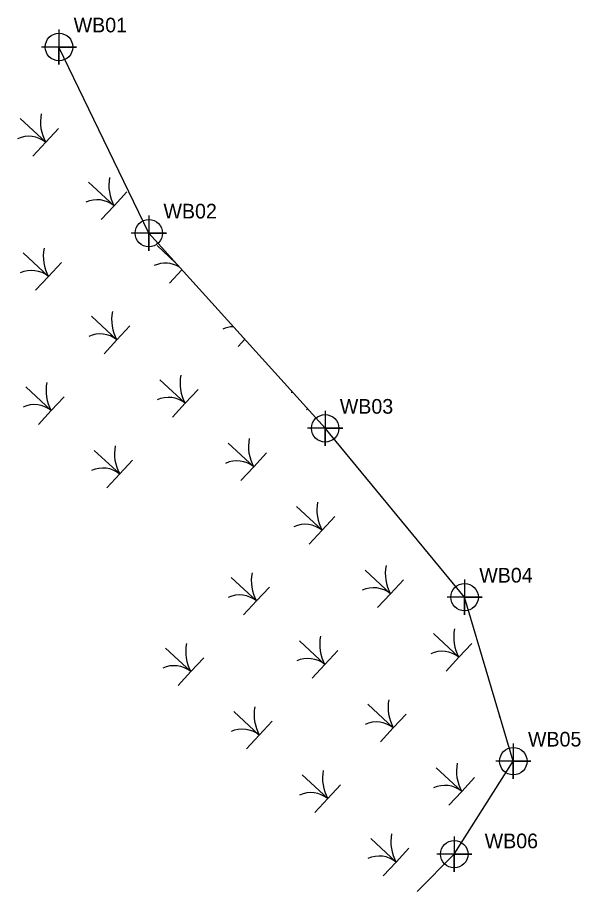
# Model space of a CAD drawing. Extents: x 2130226 to 2130625, y 149525 to 150037.
# Drawn here: x 2130401.6 to 2130497.6, y 149887.6 to 150036.7 of the extents above; entities that cross this region are included whole.
import ezdxf

# ---------------------------------------------------------------- set-up
doc = ezdxf.new("R2010")
doc.units = 0
for name, color, linetype in [('Exist Environmental Wetland Boundary', 7, 'Continuous'), ('Exist Environmental Wetland Boundary Cogo Number', 7, 'Continuous'), ('Exist Environmental Wetland Boundary Cogo Point CELL', 7, 'Continuous')]:
    doc.layers.add(name, color=color, linetype=linetype)

msp = doc.modelspace()

# ---------------------------------------------------------------- linework, layer by layer
at = {"layer": 'Exist Environmental Wetland Boundary'}
msp.add_lwpolyline([(2130469.78, 149887.64), (2130476.1, 149894), (2130486.17, 149909.87), (2130477.86, 149937.84), (2130454.07, 149966.65), (2130423.99, 149999.95), (2130408.67, 150031.7)], dxfattribs=at)
at = {"layer": 'Exist Environmental Wetland Boundary Cogo Point CELL'}
for p, q in [((2130427.54, 149991.44), (2130429.64, 149993.7)), ((2130439.21, 149980.61), (2130440.35, 149981.84)), ((2130450.88, 149969.79), (2130451.06, 149969.98))]:
    msp.add_line(p, q, dxfattribs=at)
for points in [[(2130408.67, 150034.7), (2130408.67, 150028.7), (2130408.67, 150031.7), (2130411.67, 150031.7), (2130405.67, 150031.7)], [(2130404.2, 150013.09), (2130406.4, 150015.46), (2130402.06, 150019.48), (2130406.4, 150015.46), (2130408.59, 150017.82)], [(2130415.87, 150002.27), (2130418.07, 150004.63), (2130413.73, 150008.66), (2130418.07, 150004.63), (2130420.26, 150007)], [(2130423.99, 150002.95), (2130423.99, 149996.95), (2130423.99, 149999.95), (2130426.99, 149999.95), (2130420.99, 149999.95)], [(2130428.57, 149994.88), (2130425.4, 149997.83), (2130428.57, 149994.88)], [(2130404.68, 149990.21), (2130406.88, 149992.57), (2130402.54, 149996.6), (2130406.88, 149992.57), (2130409.07, 149994.94)], [(2130416.35, 149979.38), (2130418.54, 149981.75), (2130414.21, 149985.77), (2130418.54, 149981.75), (2130420.74, 149984.11)], [(2130428.02, 149968.55), (2130430.21, 149970.92), (2130425.88, 149974.94), (2130430.21, 149970.92), (2130432.41, 149973.28)], [(2130405.16, 149967.32), (2130407.35, 149969.69), (2130403.02, 149973.71), (2130407.35, 149969.69), (2130409.55, 149972.05)], [(2130454.07, 149969.65), (2130454.07, 149963.65), (2130454.07, 149966.65), (2130457.07, 149966.65), (2130451.07, 149966.65)], [(2130416.83, 149956.49), (2130419.02, 149958.86), (2130414.69, 149962.88), (2130419.02, 149958.86), (2130421.22, 149961.22)], [(2130439.69, 149957.73), (2130441.88, 149960.09), (2130437.54, 149964.12), (2130441.88, 149960.09), (2130444.08, 149962.46)], [(2130451.36, 149946.9), (2130453.55, 149949.26), (2130449.21, 149953.29), (2130453.55, 149949.26), (2130455.74, 149951.63)], [(2130463.02, 149936.07), (2130465.22, 149938.44), (2130460.88, 149942.46), (2130465.22, 149938.44), (2130467.41, 149940.8)], [(2130440.17, 149934.84), (2130442.36, 149937.2), (2130438.02, 149941.23), (2130442.36, 149937.2), (2130444.55, 149939.57)], [(2130477.86, 149940.84), (2130477.86, 149934.84), (2130477.86, 149937.84), (2130480.86, 149937.84), (2130474.86, 149937.84)], [(2130474.69, 149925.25), (2130476.89, 149927.61), (2130472.55, 149931.63), (2130476.89, 149927.61), (2130479.08, 149929.97)], [(2130451.83, 149924.01), (2130454.03, 149926.38), (2130449.69, 149930.4), (2130454.03, 149926.38), (2130456.22, 149928.74)], [(2130428.98, 149922.78), (2130431.17, 149925.15), (2130426.83, 149929.17), (2130431.17, 149925.15), (2130433.36, 149927.51)], [(2130463.5, 149913.19), (2130465.7, 149915.55), (2130461.36, 149919.58), (2130465.7, 149915.55), (2130467.89, 149917.91)], [(2130440.64, 149911.95), (2130442.84, 149914.32), (2130438.5, 149918.34), (2130442.84, 149914.32), (2130445.03, 149916.68)], [(2130486.17, 149912.87), (2130486.17, 149906.87), (2130486.17, 149909.87), (2130489.17, 149909.87), (2130483.17, 149909.87)], [(2130475.17, 149902.36), (2130477.36, 149904.72), (2130473.03, 149908.75), (2130477.36, 149904.72), (2130479.56, 149907.09)], [(2130452.31, 149901.13), (2130454.51, 149903.49), (2130450.17, 149907.52), (2130454.51, 149903.49), (2130456.7, 149905.86)], [(2130463.98, 149890.3), (2130466.17, 149892.66), (2130461.84, 149896.69), (2130466.17, 149892.66), (2130468.37, 149895.03)], [(2130476.1, 149897), (2130476.1, 149891), (2130476.1, 149894), (2130479.1, 149894), (2130473.1, 149894)]]:
    msp.add_lwpolyline(points, dxfattribs=at)
for centre in [(2130408.67, 150031.7), (2130423.99, 149999.95), (2130454.07, 149966.65), (2130477.86, 149937.84), (2130486.17, 149909.87), (2130476.1, 149894)]:
    msp.add_circle(centre, 2.34, dxfattribs=at)
for centre, radius, start, end in [((2130412.72, 150018.93), 7.21, 169.2688, 208.7635), ((2130403.51, 150011.86), 4.61, 51.2816, 114.6763), ((2130424.39, 150008.1), 7.21, 169.2688, 208.7635), ((2130415.18, 150001.03), 4.61, 51.2816, 114.6763), ((2130413.2, 149996.04), 7.21, 169.2688, 208.7635), ((2130426.85, 149990.21), 4.61, 58.9864, 114.6763), ((2130403.99, 149988.97), 4.61, 51.2816, 114.6763), ((2130424.86, 149985.21), 7.21, 169.2688, 208.7635), ((2130438.52, 149979.38), 4.61, 91.3372, 114.6763), ((2130415.66, 149978.15), 4.61, 51.2816, 114.6763), ((2130436.53, 149974.39), 7.21, 169.2688, 208.7635), ((2130413.67, 149973.15), 7.21, 169.2688, 208.7635), ((2130427.33, 149967.32), 4.61, 51.2816, 114.6763), ((2130450.19, 149968.55), 4.61, 111.6793, 114.6763), ((2130404.47, 149966.09), 4.61, 51.2816, 114.6763), ((2130448.2, 149963.56), 7.21, 169.2688, 208.7635), ((2130425.34, 149962.33), 7.21, 169.2688, 208.7635), ((2130416.14, 149955.26), 4.61, 51.2816, 114.6763), ((2130439, 149956.49), 4.61, 51.2816, 114.6763), ((2130459.87, 149952.73), 7.21, 169.2688, 208.7635), ((2130450.66, 149945.67), 4.61, 51.2816, 114.6763), ((2130448.68, 149940.67), 7.21, 169.2688, 208.7635), ((2130471.54, 149941.91), 7.21, 169.2688, 208.7635), ((2130462.33, 149934.84), 4.61, 51.2816, 114.6763), ((2130439.47, 149933.61), 4.61, 51.2816, 114.6763), ((2130483.21, 149931.08), 7.21, 169.2688, 208.7635), ((2130460.35, 149929.85), 7.21, 169.2688, 208.7635), ((2130437.49, 149928.61), 7.21, 169.2688, 208.7635), ((2130474, 149924.01), 4.61, 51.2816, 114.6763), ((2130451.14, 149922.78), 4.61, 51.2816, 114.6763), ((2130428.28, 149921.55), 4.61, 51.2816, 114.6763), ((2130472.02, 149919.02), 7.21, 169.2688, 208.7635), ((2130449.16, 149917.79), 7.21, 169.2688, 208.7635), ((2130485.67, 149913.18), 4.61, 112.3511, 114.6763), ((2130439.95, 149910.72), 4.61, 51.2816, 114.6763), ((2130462.81, 149911.95), 4.61, 51.2816, 114.6763), ((2130483.68, 149908.19), 7.21, 169.2688, 208.7635), ((2130460.83, 149906.96), 7.21, 169.2688, 208.7635), ((2130474.48, 149901.13), 4.61, 51.2816, 114.6763), ((2130451.62, 149899.89), 4.61, 51.2816, 114.6763), ((2130472.49, 149896.13), 7.21, 169.2688, 208.7635), ((2130463.29, 149889.07), 4.61, 51.2816, 114.6763)]:
    msp.add_arc(centre, radius, start, end, dxfattribs=at)

# ---------------------------------------------------------------- texts
at = {"layer": 'Exist Environmental Wetland Boundary Cogo Number'}
for s, p in [('WB01', (2130411.17, 150034.2)), ('WB02', (2130426.49, 150002.45)), ('WB03', (2130456.57, 149969.15)), ('WB04', (2130480.36, 149940.34)), ('WB05', (2130488.67, 149912.37)), ('WB06', (2130481.28, 149895.02))]:
    msp.add_text(s, height=2.5, dxfattribs=at).set_placement(p)

doc.saveas('drawing.dxf')
